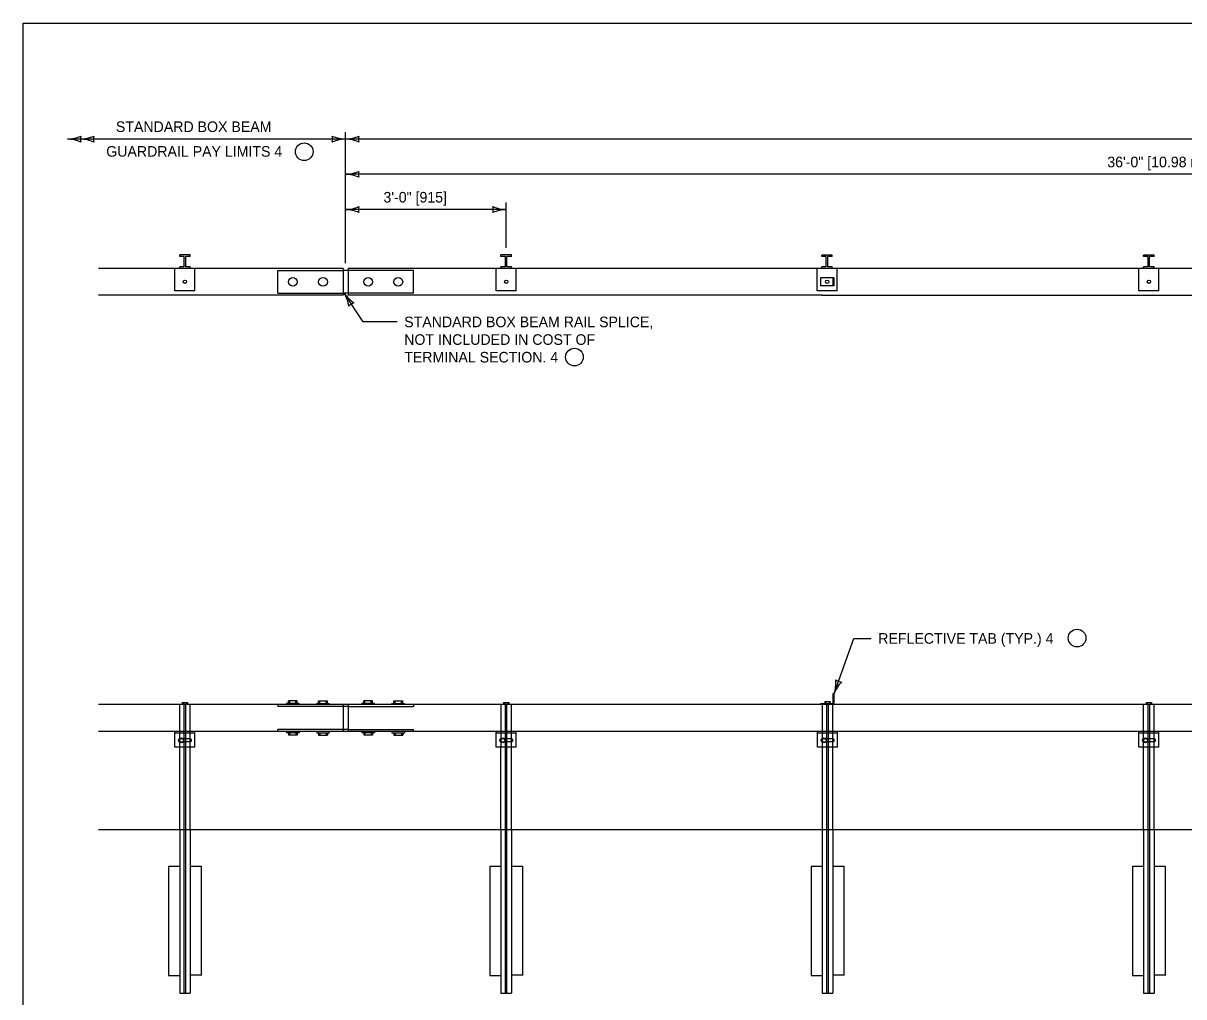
# Model space of a CAD drawing. Extents: x 49991.4 to 50021, y 49987.6 to 50011.4.
# Drawn here: x 49999.38 to 50005.97, y 49993.48 to 49999 of the extents above; entities that cross this region are included whole.
import ezdxf

# ---------------------------------------------------------------- set-up
doc = ezdxf.new("R2010")
doc.units = 0
for name, color, linetype in [('Level 1', 7, 'Continuous'), ('Level 2', 7, 'Continuous'), ('Level 3', 7, 'Continuous'), ('Level 4', 7, 'Continuous')]:
    doc.layers.add(name, color=color, linetype=linetype)

msp = doc.modelspace()

# ---------------------------------------------------------------- linework, layer by layer
at = {"layer": 'Level 1'}
for p, q in [((50000.2712, 49997.6756), (50000.2712, 49997.6848)), ((50000.3302, 49997.6848), (50000.2712, 49997.6848)), ((50000.2961, 49997.6756), (50000.2712, 49997.6756)), ((50000.2961, 49997.618), (50000.2961, 49997.6756)), ((50000.3053, 49997.618), (50000.3053, 49997.6756)), ((50000.3302, 49997.6756), (50000.3053, 49997.6756)), ((50000.3302, 49997.6756), (50000.3302, 49997.6848)), ((50002.0942, 49997.6756), (50002.0942, 49997.6848)), ((50002.1533, 49997.6848), (50002.0942, 49997.6848)), ((50002.1192, 49997.6756), (50002.0942, 49997.6756)), ((50002.1192, 49997.618), (50002.1192, 49997.6756)), ((50002.1283, 49997.618), (50002.1283, 49997.6756)), ((50002.1533, 49997.6756), (50002.1283, 49997.6756)), ((50002.1533, 49997.6756), (50002.1533, 49997.6848)), ((50003.915, 49997.6755), (50003.915, 49997.6847)), ((50003.9741, 49997.6847), (50003.915, 49997.6847)), ((50003.9401, 49997.6755), (50003.915, 49997.6755)), ((50003.9401, 49997.6179), (50003.9401, 49997.6755)), ((50003.949, 49997.6179), (50003.949, 49997.6755)), ((50003.9741, 49997.6755), (50003.949, 49997.6755)), ((50003.9741, 49997.6755), (50003.9741, 49997.6847)), ((50005.7405, 49997.6755), (50005.7405, 49997.6847)), ((50005.7996, 49997.6847), (50005.7405, 49997.6847)), ((50005.7655, 49997.6755), (50005.7405, 49997.6755)), ((50005.7655, 49997.6179), (50005.7655, 49997.6755)), ((50005.7746, 49997.6179), (50005.7746, 49997.6755)), ((50005.7996, 49997.6755), (50005.7746, 49997.6755)), ((50005.7996, 49997.6755), (50005.7996, 49997.6847)), ((50001.1982, 49997.6088), (49999.8098, 49997.6088)), ((50000.2961, 49997.618), (50000.2712, 49997.618)), ((50000.2712, 49997.6088), (50000.2712, 49997.618)), ((50000.3302, 49997.618), (50000.3053, 49997.618)), ((50000.3302, 49997.6088), (50000.3302, 49997.618)), ((50001.1982, 49997.6087), (50001.1982, 49997.4569)), ((50001.2265, 49997.5975), (50001.1982, 49997.5975)), ((50001.2265, 49997.6087), (50001.2265, 49997.4568)), ((50006.6846, 49997.6087), (50001.2265, 49997.6087)), ((50002.1192, 49997.618), (50002.0942, 49997.618)), ((50002.0942, 49997.6088), (50002.0942, 49997.618)), ((50002.1533, 49997.618), (50002.1283, 49997.618)), ((50002.1533, 49997.6088), (50002.1533, 49997.618)), ((50003.9401, 49997.6179), (50003.915, 49997.6179)), ((50003.915, 49997.6087), (50003.915, 49997.6179)), ((50003.9741, 49997.6179), (50003.949, 49997.6179)), ((50003.9741, 49997.6087), (50003.9741, 49997.6179)), ((50005.7655, 49997.6179), (50005.7405, 49997.6179)), ((50005.7405, 49997.6087), (50005.7405, 49997.6179)), ((50005.7996, 49997.6179), (50005.7746, 49997.6179)), ((50005.7996, 49997.6087), (50005.7996, 49997.6179)), ((50003.907, 49997.555), (50003.907, 49997.5106)), ((50003.9829, 49997.555), (50003.907, 49997.555)), ((50003.9766, 49997.555), (50003.9766, 49997.5106)), ((50003.9829, 49997.555), (50003.9829, 49997.5106)), ((50001.1982, 49997.4569), (49999.8098, 49997.4569)), ((50001.2265, 49997.468), (50001.1982, 49997.4681)), ((50003.9174, 49997.4568), (50001.2265, 49997.4568)), ((50003.9829, 49997.5106), (50003.907, 49997.5106)), ((50000.2852, 49995.146), (50000.3165, 49995.146)), ((50000.2852, 49995.146), (50000.2852, 49995.1348)), ((50000.2921, 49995.146), (50000.2921, 49995.1348)), ((50000.3099, 49995.146), (50000.3099, 49995.1348)), ((50000.3165, 49995.146), (50000.3165, 49995.1348)), ((50000.8884, 49995.142), (50000.8884, 49995.1562)), ((50000.9382, 49995.1562), (50000.8884, 49995.1562)), ((50000.8954, 49995.142), (50000.8954, 49995.1562)), ((50000.9311, 49995.142), (50000.9311, 49995.1562)), ((50000.9382, 49995.142), (50000.9382, 49995.1562)), ((50001.0592, 49995.1562), (50001.1091, 49995.1562)), ((50001.0592, 49995.142), (50001.0592, 49995.1562)), ((50001.0663, 49995.142), (50001.0663, 49995.1562)), ((50001.102, 49995.142), (50001.102, 49995.1562)), ((50001.1091, 49995.142), (50001.1091, 49995.1562)), ((50001.3655, 49995.1562), (50001.3156, 49995.1562)), ((50001.3156, 49995.142), (50001.3156, 49995.1562)), ((50001.3227, 49995.142), (50001.3227, 49995.1562)), ((50001.3584, 49995.142), (50001.3584, 49995.1562)), ((50001.3655, 49995.142), (50001.3655, 49995.1562)), ((50001.4865, 49995.1562), (50001.5365, 49995.1562)), ((50001.4865, 49995.142), (50001.4865, 49995.1562)), ((50001.4936, 49995.142), (50001.4936, 49995.1562)), ((50001.5293, 49995.142), (50001.5293, 49995.1562)), ((50001.5365, 49995.142), (50001.5365, 49995.1562)), ((50002.1084, 49995.146), (50002.1397, 49995.146)), ((50002.1084, 49995.146), (50002.1084, 49995.1348)), ((50002.1152, 49995.146), (50002.1152, 49995.1348)), ((50002.1329, 49995.146), (50002.1329, 49995.1348)), ((50002.1397, 49995.146), (50002.1397, 49995.1348)), ((50003.9314, 49995.1523), (50003.9628, 49995.1523)), ((50003.9314, 49995.1523), (50003.9314, 49995.1411)), ((50003.9383, 49995.1523), (50003.9383, 49995.1411)), ((50003.9561, 49995.1523), (50003.9561, 49995.1411)), ((50003.9628, 49995.1523), (50003.9628, 49995.1411)), ((50003.9787, 49995.1981), (50003.985, 49995.1981)), ((50003.9787, 49995.1411), (50003.9787, 49995.1981)), ((50003.985, 49995.1348), (50003.985, 49995.1981)), ((50005.7547, 49995.146), (50005.786, 49995.146)), ((50005.7547, 49995.146), (50005.7547, 49995.1348)), ((50005.7615, 49995.146), (50005.7615, 49995.1348)), ((50005.7792, 49995.146), (50005.7792, 49995.1348)), ((50005.786, 49995.146), (50005.786, 49995.1348)), ((50001.1981, 49995.1348), (49999.8098, 49995.1348)), ((50000.9487, 49995.142), (50000.8777, 49995.142)), ((50000.8777, 49995.1349), (50000.8777, 49995.142)), ((50000.9487, 49995.1349), (50000.9487, 49995.142)), ((50001.0485, 49995.142), (50001.1196, 49995.142)), ((50001.0485, 49995.1349), (50001.0485, 49995.142)), ((50001.1196, 49995.1349), (50001.1196, 49995.142)), ((50001.1981, 49995.1348), (50001.1981, 49994.9829)), ((50001.2264, 49995.1348), (50001.1981, 49995.1348)), ((50001.2264, 49995.1236), (50001.1981, 49995.1236)), ((50001.2264, 49995.1348), (50001.2264, 49994.9829)), ((50012.2287, 49995.1348), (50001.2264, 49995.1348)), ((50001.3761, 49995.142), (50001.3049, 49995.142)), ((50001.3049, 49995.1349), (50001.3049, 49995.142)), ((50001.3761, 49995.1349), (50001.3761, 49995.142)), ((50001.4759, 49995.142), (50001.547, 49995.142)), ((50001.4759, 49995.1349), (50001.4759, 49995.142)), ((50001.547, 49995.1349), (50001.547, 49995.142)), ((50003.9091, 49995.1348), (50003.9091, 49995.1411)), ((50003.9091, 49995.1411), (50003.9787, 49995.1411)), ((50001.1981, 49994.9829), (49999.8098, 49994.9829)), ((50000.2439, 49994.8943), (50000.2439, 49994.9829)), ((50000.3578, 49994.9734), (50000.2439, 49994.9734)), ((50000.3578, 49994.8943), (50000.3578, 49994.9829)), ((50000.8777, 49994.9829), (50000.8777, 49994.9758)), ((50000.9487, 49994.9758), (50000.8777, 49994.9758)), ((50000.8884, 49994.9758), (50000.8884, 49994.9616)), ((50000.9382, 49994.9616), (50000.8884, 49994.9616)), ((50000.8954, 49994.9758), (50000.8954, 49994.9616)), ((50000.9311, 49994.9758), (50000.9311, 49994.9616)), ((50000.9382, 49994.9758), (50000.9382, 49994.9616)), ((50000.9487, 49994.9829), (50000.9487, 49994.9758)), ((50001.0485, 49994.9829), (50001.0485, 49994.9758)), ((50001.0485, 49994.9758), (50001.1196, 49994.9758)), ((50001.0592, 49994.9758), (50001.0592, 49994.9616)), ((50001.0592, 49994.9616), (50001.1091, 49994.9616)), ((50001.0663, 49994.9758), (50001.0663, 49994.9616)), ((50001.102, 49994.9758), (50001.102, 49994.9616)), ((50001.1091, 49994.9758), (50001.1091, 49994.9616)), ((50001.1196, 49994.9829), (50001.1196, 49994.9758)), ((50001.2264, 49994.9941), (50001.1981, 49994.9941)), ((50001.2264, 49994.9829), (50001.1981, 49994.9829)), ((50012.2287, 49994.9829), (50001.2264, 49994.9829)), ((50001.3049, 49994.9829), (50001.3049, 49994.9758)), ((50001.3761, 49994.9758), (50001.3049, 49994.9758)), ((50001.3156, 49994.9758), (50001.3156, 49994.9616)), ((50001.3655, 49994.9616), (50001.3156, 49994.9616)), ((50001.3227, 49994.9758), (50001.3227, 49994.9616)), ((50001.3584, 49994.9758), (50001.3584, 49994.9616)), ((50001.3655, 49994.9758), (50001.3655, 49994.9616)), ((50001.3761, 49994.9829), (50001.3761, 49994.9758)), ((50001.4759, 49994.9829), (50001.4759, 49994.9758)), ((50001.4759, 49994.9758), (50001.547, 49994.9758)), ((50001.4865, 49994.9758), (50001.4865, 49994.9616)), ((50001.4865, 49994.9616), (50001.5365, 49994.9616)), ((50001.4936, 49994.9758), (50001.4936, 49994.9616)), ((50001.5293, 49994.9758), (50001.5293, 49994.9616)), ((50001.5365, 49994.9758), (50001.5365, 49994.9616)), ((50001.547, 49994.9829), (50001.547, 49994.9758)), ((50002.067, 49994.8943), (50002.067, 49994.9829)), ((50002.181, 49994.9734), (50002.067, 49994.9734)), ((50002.181, 49994.8943), (50002.181, 49994.9829)), ((50003.8902, 49994.8943), (50003.8902, 49994.9829)), ((50004.0041, 49994.9734), (50003.8902, 49994.9734)), ((50004.0041, 49994.8943), (50004.0041, 49994.9829)), ((50005.7133, 49994.8944), (50005.7133, 49994.9829)), ((50005.8273, 49994.9734), (50005.7133, 49994.9734)), ((50005.8273, 49994.8944), (50005.8273, 49994.9829)), ((50000.3578, 49994.8943), (50000.2439, 49994.8943)), ((50000.2713, 49994.4259), (50000.2713, 49994.8943)), ((50000.3303, 49994.9402), (50000.2927, 49994.9402)), ((50000.3307, 49994.9244), (50000.2928, 49994.9244)), ((50000.3303, 49994.4259), (50000.3303, 49994.8943)), ((50002.181, 49994.8943), (50002.067, 49994.8943)), ((50002.0943, 49994.4259), (50002.0943, 49994.8943)), ((50002.1535, 49994.9402), (50002.1159, 49994.9402)), ((50002.154, 49994.9244), (50002.116, 49994.9244)), ((50002.1535, 49994.4259), (50002.1535, 49994.8943)), ((50004.0041, 49994.8943), (50003.8902, 49994.8943)), ((50003.9176, 49994.4258), (50003.9176, 49994.8943)), ((50003.9766, 49994.9402), (50003.9389, 49994.9402)), ((50003.9771, 49994.9244), (50003.9391, 49994.9244)), ((50003.9766, 49994.4258), (50003.9766, 49994.8943)), ((50005.8273, 49994.8944), (50005.7133, 49994.8944)), ((50005.7406, 49994.4258), (50005.7406, 49994.8943)), ((50005.7997, 49994.9402), (50005.7621, 49994.9402)), ((50005.8003, 49994.9244), (50005.7623, 49994.9244)), ((50005.7997, 49994.4258), (50005.7997, 49994.8943)), ((49999.8098, 49994.4259), (50016.5942, 49994.4259))]:
    msp.add_line(p, q, dxfattribs=at)
for points in [[(49999.3835, 49998.9992), (50016.7501, 49998.9992), (50016.7501, 49987.7988), (49999.3835, 49987.7988)], [(50000.2757, 49994.9431), (50000.2881, 49994.943), (50000.2942, 49994.9322), (50000.2878, 49994.9216), (50000.2755, 49994.9218), (50000.2695, 49994.9325)], [(50002.099, 49994.9431), (50002.1112, 49994.943), (50002.1172, 49994.9322), (50002.1111, 49994.9216), (50002.0987, 49994.9218), (50002.0926, 49994.9325)], [(50003.922, 49994.9431), (50003.9343, 49994.943), (50003.9404, 49994.9322), (50003.9342, 49994.9216), (50003.9218, 49994.9218), (50003.9158, 49994.9325)], [(50005.7451, 49994.9431), (50005.7576, 49994.943), (50005.7635, 49994.9322), (50005.7572, 49994.9216), (50005.745, 49994.9218), (50005.7389, 49994.9325)]]:
    msp.add_lwpolyline(points, close=True, dxfattribs=at)
msp.add_lwpolyline([(50003.915, 49997.4568), (50006.6846, 49997.4568)], dxfattribs=at)
for centre, radius in [((50000.3007, 49997.5329), 0.00948), ((50000.9134, 49997.5327), 0.0249), ((50001.0843, 49997.5327), 0.0249), ((50001.3406, 49997.5327), 0.0249), ((50001.5116, 49997.5327), 0.0249), ((50002.124, 49997.5329), 0.00948), ((50003.945, 49997.5328), 0.00948), ((50005.7702, 49997.5328), 0.00948), ((50000.2819, 49994.9322), 0.0135), ((50002.105, 49994.9322), 0.0135), ((50003.9282, 49994.9322), 0.0135), ((50005.7513, 49994.9322), 0.0135)]:
    msp.add_circle(centre, radius, dxfattribs=at)
for centre, start, end in [((50000.2708, 49994.9323), 88.99088, 270.27808), ((50000.3309, 49994.9323), 269.72192, 91.00912), ((50002.0939, 49994.9323), 88.99088, 270.27808), ((50002.154, 49994.9323), 269.72192, 91.00912), ((50003.9171, 49994.9323), 88.99088, 270.27808), ((50003.9772, 49994.9323), 269.72192, 91.00912), ((50005.7402, 49994.9323), 88.99088, 270.27808), ((50005.8003, 49994.9323), 269.72192, 91.00912)]:
    msp.add_arc(centre, 0.00794, start, end, dxfattribs=at)
at = {"layer": 'Level 2'}
for centre in [(50000.9779, 49998.2706), (50002.5111, 49997.1059), (50005.363, 49995.5124)]:
    msp.add_circle(centre, 0.05, dxfattribs=at)
at = {"layer": 'Level 3'}
for p, q in [((50001.2124, 49997.6375), (50001.2124, 49998.3823)), ((50001.2124, 49998.3423), (49999.635, 49998.3423)), ((50015.7531, 49998.3423), (50001.2124, 49998.3423)), ((50012.2286, 49998.1423), (50001.2124, 49998.1423)), ((50002.1238, 49997.7248), (50002.1238, 49997.9823)), ((50002.1238, 49997.9423), (50001.2124, 49997.9423)), ((50001.3116, 49997.3052), (50001.2048, 49997.4681)), ((50001.5053, 49997.3052), (50001.3116, 49997.3052)), ((50003.985, 49995.1981), (50004.0967, 49995.5102)), ((50004.0967, 49995.5102), (50004.1948, 49995.5102))]:
    msp.add_line(p, q, dxfattribs=at)
for centre, radius, start, end in [((49999.6235, 49998.575), 0.233, 272.82731, 292.07716), ((49999.6258, 49998.1201), 0.2223, 67.45601, 87.63952), ((49999.7632, 49998.3423), 0.0548, 162.13882, 197.86118), ((49999.6969, 49998.575), 0.233, 272.82731, 292.07716), ((49999.6992, 49998.1201), 0.2223, 67.45601, 87.63952), ((49999.8366, 49998.3423), 0.0548, 162.13882, 197.86118), ((50001.2216, 49998.5644), 0.2223, 247.45601, 267.63952), ((50001.0842, 49998.3423), 0.0548, 342.13882, 17.86118), ((50001.2239, 49998.1096), 0.233, 92.82731, 112.07716), ((50001.2009, 49998.575), 0.233, 272.82731, 292.07716), ((50001.2032, 49998.1201), 0.2223, 67.45601, 87.63952), ((50001.3406, 49998.3423), 0.0548, 162.13882, 197.86118), ((50001.2009, 49998.375), 0.233, 272.82731, 292.07716), ((50001.2032, 49997.9201), 0.2223, 67.45601, 87.63952), ((50001.3406, 49998.1423), 0.0548, 162.13882, 197.86118), ((50001.2009, 49998.175), 0.233, 272.82731, 292.07716), ((50001.2032, 49997.7202), 0.2223, 67.45601, 87.63952), ((50001.3406, 49997.9423), 0.0548, 162.13882, 197.86118), ((50002.133, 49998.1644), 0.2223, 247.45601, 267.63952), ((50001.9956, 49997.9423), 0.0548, 342.13882, 17.86118), ((50002.1353, 49997.7096), 0.233, 92.82731, 112.07716), ((50001.0127, 49997.3562), 0.2223, 10.01531, 30.19882), ((50001.3948, 49997.603), 0.233, 215.38661, 234.63646), ((50001.2738, 49997.36), 0.0548, 104.69812, 140.42048), ((50003.762, 49995.2657), 0.233, 343.12487, 2.37472), ((50004.191, 49995.1146), 0.2223, 137.75357, 157.93708), ((50004.0282, 49995.3188), 0.0548, 232.43638, 268.15874)]:
    msp.add_arc(centre, radius, start, end, dxfattribs=at)
at = {"layer": 'Level 4'}
for p, q in [((50000.2436, 49997.4821), (50000.2436, 49997.6088)), ((50000.3576, 49997.4821), (50000.3576, 49997.6088)), ((50000.8278, 49997.468), (50000.8278, 49997.5975)), ((50000.8278, 49997.5975), (50001.1982, 49997.5975)), ((50001.597, 49997.5975), (50001.2265, 49997.5975)), ((50001.597, 49997.4681), (50001.597, 49997.5975)), ((50002.0668, 49997.4821), (50002.0668, 49997.6088)), ((50002.1807, 49997.4821), (50002.1807, 49997.6088)), ((50003.8876, 49997.482), (50003.8876, 49997.6087)), ((50004.0017, 49997.482), (50004.0017, 49997.6087)), ((50005.713, 49997.4821), (50005.713, 49997.6087)), ((50005.827, 49997.4821), (50005.827, 49997.6087)), ((50000.3576, 49997.4821), (50000.2436, 49997.4821)), ((50000.8278, 49997.468), (50001.1982, 49997.4681)), ((50001.597, 49997.4681), (50001.2265, 49997.468)), ((50002.1807, 49997.4821), (50002.0668, 49997.4821)), ((50004.0017, 49997.4821), (50003.8876, 49997.4821)), ((50005.827, 49997.4821), (50005.713, 49997.4821)), ((50000.2713, 49994.8943), (50000.2713, 49995.1348)), ((50000.2961, 49993.498), (50000.2961, 49995.1348)), ((50000.3054, 49993.498), (50000.3054, 49995.1348)), ((50000.3305, 49994.8943), (50000.3305, 49995.1348)), ((50000.8278, 49995.1348), (50000.8278, 49995.1236)), ((50001.1981, 49995.1236), (50000.8278, 49995.1236)), ((50001.2264, 49995.1236), (50001.597, 49995.1236)), ((50001.597, 49995.1348), (50001.597, 49995.1236)), ((50002.0944, 49994.8943), (50002.0944, 49995.1348)), ((50002.1193, 49993.498), (50002.1193, 49995.1348)), ((50002.1284, 49993.498), (50002.1284, 49995.1348)), ((50002.1536, 49994.8943), (50002.1536, 49995.1348)), ((50003.9176, 49994.8944), (50003.9176, 49995.1348)), ((50003.9426, 49993.498), (50003.9426, 49995.1348)), ((50003.9516, 49993.498), (50003.9516, 49995.1348)), ((50003.9767, 49994.8944), (50003.9767, 49995.1348)), ((50005.7406, 49994.8944), (50005.7406, 49995.1348)), ((50005.7656, 49993.498), (50005.7656, 49995.1348)), ((50005.7748, 49993.498), (50005.7748, 49995.1348)), ((50005.7997, 49994.8944), (50005.7997, 49995.1348)), ((50001.1981, 49994.9941), (50000.8278, 49994.9941)), ((50000.8278, 49994.9829), (50000.8278, 49994.9941)), ((50001.2264, 49994.9941), (50001.597, 49994.9941)), ((50001.597, 49994.9829), (50001.597, 49994.9941)), ((50000.2713, 49994.4259), (50000.2713, 49993.498)), ((50000.3302, 49994.4259), (50000.3302, 49993.498)), ((50002.0943, 49994.4259), (50002.0943, 49993.498)), ((50002.1534, 49994.4259), (50002.1534, 49993.498)), ((50003.9175, 49994.4258), (50003.9175, 49993.498)), ((50003.9766, 49994.4258), (50003.9766, 49993.498)), ((50005.7406, 49994.4258), (50005.7406, 49993.498)), ((50005.7997, 49994.4258), (50005.7997, 49993.498)), ((50000.2079, 49994.2178), (50000.2713, 49994.2178)), ((50000.2079, 49994.2178), (50000.2079, 49993.5993)), ((50000.3302, 49994.2178), (50000.3935, 49994.2178)), ((50000.3935, 49994.2178), (50000.3935, 49993.5993)), ((50002.0311, 49994.2178), (50002.0943, 49994.2178)), ((50002.0311, 49994.2178), (50002.0311, 49993.5993)), ((50002.1534, 49994.2178), (50002.2167, 49994.2178)), ((50002.2167, 49994.2178), (50002.2167, 49993.5993)), ((50003.8542, 49994.2178), (50003.9175, 49994.2178)), ((50003.8542, 49994.2178), (50003.8542, 49993.5993)), ((50003.9766, 49994.2178), (50004.0397, 49994.2178)), ((50004.0397, 49994.2178), (50004.0397, 49993.5993)), ((50005.6773, 49994.2178), (50005.7406, 49994.2178)), ((50005.6773, 49994.2178), (50005.6773, 49993.5993)), ((50005.7997, 49994.2178), (50005.8629, 49994.2178)), ((50005.8629, 49994.2178), (50005.8629, 49993.5993)), ((50000.2079, 49993.5993), (50000.2713, 49993.5993)), ((50000.3302, 49993.6027), (50000.3935, 49993.6027)), ((50002.0311, 49993.5993), (50002.0943, 49993.5993)), ((50002.1534, 49993.6027), (50002.2167, 49993.6027)), ((50003.8542, 49993.5993), (50003.9175, 49993.5993)), ((50003.9766, 49993.6027), (50004.0397, 49993.6027)), ((50005.6773, 49993.5993), (50005.7406, 49993.5993)), ((50005.7997, 49993.6027), (50005.8629, 49993.6027)), ((50000.2713, 49993.498), (50000.3302, 49993.498)), ((50002.0943, 49993.498), (50002.1534, 49993.498)), ((50003.9175, 49993.498), (50003.9766, 49993.498)), ((50005.7406, 49993.498), (50005.7997, 49993.498))]:
    msp.add_line(p, q, dxfattribs=at)

# ---------------------------------------------------------------- texts
at = {"layer": 'Level 2'}
for s, p in [('STANDARD BOX BEAM ', (49999.9094, 49998.3823)), ('GUARDRAIL PAY LIMITS 4', (49999.8546, 49998.2423)), ('36\'-0" [10.98 m] STANDARD BOX BEAM GUARDRAIL 4', (50005.5342, 49998.1823)), ('3\'-0" [915]', (50001.4275, 49997.9823)), ('STANDARD BOX BEAM RAIL SPLICE,', (50001.5453, 49997.2752)), ('NOT INCLUDED IN COST OF', (50001.5453, 49997.1752)), ('TERMINAL SECTION. 4', (50001.5453, 49997.0752)), ('REFLECTIVE TAB (TYP.) 4 ', (50004.2348, 49995.4802))]:
    msp.add_text(s, height=0.06, dxfattribs=at).set_placement(p)

doc.saveas('drawing.dxf')
